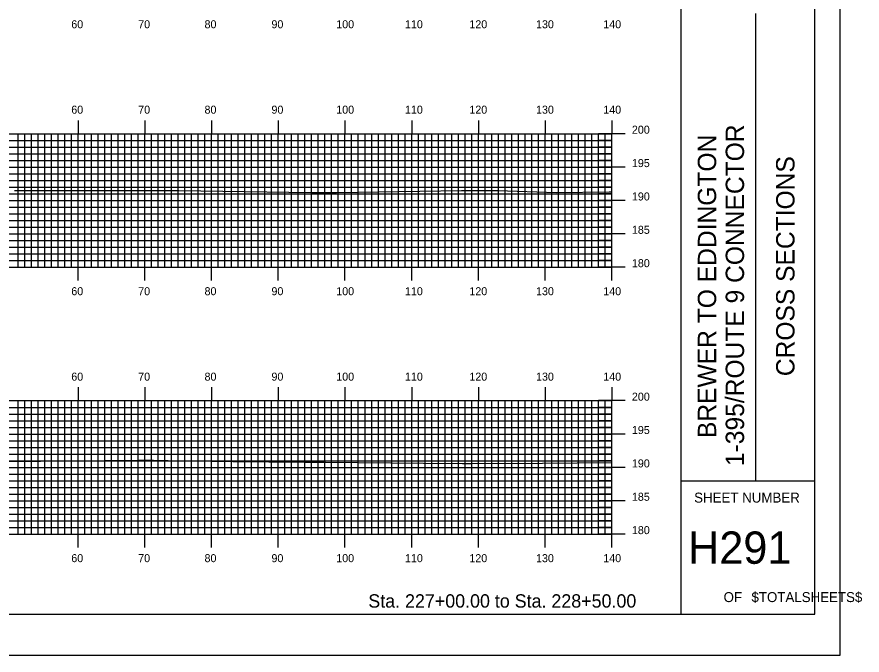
# Model space of a CAD drawing. Extents: x 1798781 to 1799124, y 442591 to 442811.
# Drawn here: x 1798997.8 to 1799124.5, y 442590.5 to 442686.2 of the extents above; entities that cross this region are included whole.
import ezdxf

# ---------------------------------------------------------------- set-up
doc = ezdxf.new("R2010")
doc.units = 0
for name, color, linetype in [('BORDER', 7, 'Continuous'), ('H_V ANNOTATION', 7, 'Continuous'), ('MAJOR', 7, 'Continuous'), ('MINOR', 7, 'Continuous'), ('PLOT BOUNDARY', 7, 'Continuous'), ('S_Roadway_Centerline', 7, 'Continuous')]:
    doc.layers.add(name, color=color, linetype=linetype)

msp = doc.modelspace()

# ---------------------------------------------------------------- linework, layer by layer
at = {"layer": 'BORDER'}
for p, q in [((1799097.38, 442596.67), (1799097.38, 442806.67)), ((1799108.57, 442616.67), (1799108.57, 442686.67)), ((1799097.38, 442616.67), (1799117.38, 442616.67))]:
    msp.add_line(p, q, dxfattribs=at)
msp.add_lwpolyline([(1798797.38, 442596.67), (1799117.38, 442596.67), (1799117.38, 442806.67), (1798797.38, 442806.67)], close=True, dxfattribs=at)
at = {"layer": 'MAJOR'}
for p, q in [((1799006.98, 442670.67), (1799006.98, 442668.67)), ((1799016.98, 442670.67), (1799016.98, 442668.67)), ((1799026.98, 442670.67), (1799026.98, 442668.67)), ((1799036.98, 442670.67), (1799036.98, 442668.67)), ((1799046.98, 442670.67), (1799046.98, 442668.67)), ((1799056.98, 442670.67), (1799056.98, 442668.67)), ((1799066.98, 442670.67), (1799066.98, 442668.67)), ((1799076.98, 442670.67), (1799076.98, 442668.67)), ((1799086.98, 442670.67), (1799086.98, 442668.67)), ((1798806.98, 442668.67), (1799086.98, 442668.67)), ((1798806.98, 442668.67), (1799086.98, 442668.67)), ((1799006.98, 442648.67), (1799006.98, 442668.67)), ((1799016.98, 442648.67), (1799016.98, 442668.67)), ((1799026.98, 442648.67), (1799026.98, 442668.67)), ((1799036.98, 442648.67), (1799036.98, 442668.67)), ((1799046.98, 442648.67), (1799046.98, 442668.67)), ((1799056.98, 442648.67), (1799056.98, 442668.67)), ((1799066.98, 442648.67), (1799066.98, 442668.67)), ((1799076.98, 442648.67), (1799076.98, 442668.67)), ((1799088.99, 442668.67), (1799084.98, 442668.67)), ((1799086.98, 442648.67), (1799086.98, 442668.67)), ((1799086.98, 442648.67), (1799086.98, 442668.67)), ((1798806.98, 442663.67), (1799086.98, 442663.67)), ((1799088.99, 442663.67), (1799084.98, 442663.67)), ((1798806.98, 442658.67), (1799086.98, 442658.67)), ((1799088.99, 442658.67), (1799084.98, 442658.67)), ((1798806.98, 442653.67), (1799086.98, 442653.67)), ((1799088.99, 442653.67), (1799084.98, 442653.67)), ((1798806.98, 442648.67), (1799086.98, 442648.67)), ((1798806.98, 442648.67), (1799086.98, 442648.67)), ((1799006.98, 442646.66), (1799006.98, 442648.67)), ((1799016.98, 442646.66), (1799016.98, 442648.67)), ((1799026.98, 442646.66), (1799026.98, 442648.67)), ((1799036.98, 442646.66), (1799036.98, 442648.67)), ((1799046.98, 442646.66), (1799046.98, 442648.67)), ((1799056.98, 442646.66), (1799056.98, 442648.67)), ((1799066.98, 442646.66), (1799066.98, 442648.67)), ((1799076.98, 442646.66), (1799076.98, 442648.67)), ((1799088.99, 442648.67), (1799084.98, 442648.67)), ((1799086.98, 442646.66), (1799086.98, 442648.67)), ((1799006.98, 442630.67), (1799006.98, 442628.67)), ((1799016.98, 442630.67), (1799016.98, 442628.67)), ((1799026.98, 442630.67), (1799026.98, 442628.67)), ((1799036.98, 442630.67), (1799036.98, 442628.67)), ((1799046.98, 442630.67), (1799046.98, 442628.67)), ((1799056.98, 442630.67), (1799056.98, 442628.67)), ((1799066.98, 442630.67), (1799066.98, 442628.67)), ((1799076.98, 442630.67), (1799076.98, 442628.67)), ((1799086.98, 442630.67), (1799086.98, 442628.67)), ((1798806.98, 442628.67), (1799086.98, 442628.67)), ((1798806.98, 442628.67), (1799086.98, 442628.67)), ((1799006.98, 442608.67), (1799006.98, 442628.67)), ((1799016.98, 442608.67), (1799016.98, 442628.67)), ((1799026.98, 442608.67), (1799026.98, 442628.67)), ((1799036.98, 442608.67), (1799036.98, 442628.67)), ((1799046.98, 442608.67), (1799046.98, 442628.67)), ((1799056.98, 442608.67), (1799056.98, 442628.67)), ((1799066.98, 442608.67), (1799066.98, 442628.67)), ((1799076.98, 442608.67), (1799076.98, 442628.67)), ((1799088.99, 442628.67), (1799084.98, 442628.67)), ((1799086.98, 442608.67), (1799086.98, 442628.67)), ((1799086.98, 442608.67), (1799086.98, 442628.67)), ((1798806.98, 442623.67), (1799086.98, 442623.67)), ((1799088.99, 442623.67), (1799084.98, 442623.67)), ((1798806.98, 442618.67), (1799086.98, 442618.67)), ((1799088.99, 442618.67), (1799084.98, 442618.67)), ((1798806.98, 442613.67), (1799086.98, 442613.67)), ((1799088.99, 442613.67), (1799084.98, 442613.67)), ((1798806.98, 442608.67), (1799086.98, 442608.67)), ((1798806.98, 442608.67), (1799086.98, 442608.67)), ((1799006.98, 442606.66), (1799006.98, 442608.67)), ((1799016.98, 442606.66), (1799016.98, 442608.67)), ((1799026.98, 442606.66), (1799026.98, 442608.67)), ((1799036.98, 442606.66), (1799036.98, 442608.67)), ((1799046.98, 442606.66), (1799046.98, 442608.67)), ((1799056.98, 442606.66), (1799056.98, 442608.67)), ((1799066.98, 442606.66), (1799066.98, 442608.67)), ((1799076.98, 442606.66), (1799076.98, 442608.67)), ((1799088.99, 442608.67), (1799084.98, 442608.67)), ((1799086.98, 442606.66), (1799086.98, 442608.67))]:
    msp.add_line(p, q, dxfattribs=at)
at = {"layer": 'MINOR'}
for p, q in [((1798997.98, 442648.67), (1798997.98, 442668.67)), ((1798998.98, 442648.67), (1798998.98, 442668.67)), ((1798999.98, 442648.67), (1798999.98, 442668.67)), ((1799000.98, 442648.67), (1799000.98, 442668.67)), ((1799001.98, 442648.67), (1799001.98, 442668.67)), ((1799002.98, 442648.67), (1799002.98, 442668.67)), ((1799003.98, 442648.67), (1799003.98, 442668.67)), ((1799004.98, 442648.67), (1799004.98, 442668.67)), ((1799005.98, 442648.67), (1799005.98, 442668.67)), ((1799007.98, 442648.67), (1799007.98, 442668.67)), ((1799008.98, 442648.67), (1799008.98, 442668.67)), ((1799009.98, 442648.67), (1799009.98, 442668.67)), ((1799010.98, 442648.67), (1799010.98, 442668.67)), ((1799011.98, 442648.67), (1799011.98, 442668.67)), ((1799012.98, 442648.67), (1799012.98, 442668.67)), ((1799013.98, 442648.67), (1799013.98, 442668.67)), ((1799014.98, 442648.67), (1799014.98, 442668.67)), ((1799015.98, 442648.67), (1799015.98, 442668.67)), ((1799017.98, 442648.67), (1799017.98, 442668.67)), ((1799018.98, 442648.67), (1799018.98, 442668.67)), ((1799019.98, 442648.67), (1799019.98, 442668.67)), ((1799020.98, 442648.67), (1799020.98, 442668.67)), ((1799021.98, 442648.67), (1799021.98, 442668.67)), ((1799022.98, 442648.67), (1799022.98, 442668.67)), ((1799023.98, 442648.67), (1799023.98, 442668.67)), ((1799024.98, 442648.67), (1799024.98, 442668.67)), ((1799025.98, 442648.67), (1799025.98, 442668.67)), ((1799027.98, 442648.67), (1799027.98, 442668.67)), ((1799028.98, 442648.67), (1799028.98, 442668.67)), ((1799029.98, 442648.67), (1799029.98, 442668.67)), ((1799030.98, 442648.67), (1799030.98, 442668.67)), ((1799031.98, 442648.67), (1799031.98, 442668.67)), ((1799032.98, 442648.67), (1799032.98, 442668.67)), ((1799033.98, 442648.67), (1799033.98, 442668.67)), ((1799034.98, 442648.67), (1799034.98, 442668.67)), ((1799035.98, 442648.67), (1799035.98, 442668.67)), ((1799037.98, 442648.67), (1799037.98, 442668.67)), ((1799038.98, 442648.67), (1799038.98, 442668.67)), ((1799039.98, 442648.67), (1799039.98, 442668.67)), ((1799040.98, 442648.67), (1799040.98, 442668.67)), ((1799041.98, 442648.67), (1799041.98, 442668.67)), ((1799042.98, 442648.67), (1799042.98, 442668.67)), ((1799043.98, 442648.67), (1799043.98, 442668.67)), ((1799044.98, 442648.67), (1799044.98, 442668.67)), ((1799045.98, 442648.67), (1799045.98, 442668.67)), ((1799047.98, 442648.67), (1799047.98, 442668.67)), ((1799048.98, 442648.67), (1799048.98, 442668.67)), ((1799049.98, 442648.67), (1799049.98, 442668.67)), ((1799050.98, 442648.67), (1799050.98, 442668.67)), ((1799051.98, 442648.67), (1799051.98, 442668.67)), ((1799052.98, 442648.67), (1799052.98, 442668.67)), ((1799053.98, 442648.67), (1799053.98, 442668.67)), ((1799054.98, 442648.67), (1799054.98, 442668.67)), ((1799055.98, 442648.67), (1799055.98, 442668.67)), ((1799057.98, 442648.67), (1799057.98, 442668.67)), ((1799058.98, 442648.67), (1799058.98, 442668.67)), ((1799059.98, 442648.67), (1799059.98, 442668.67)), ((1799060.98, 442648.67), (1799060.98, 442668.67)), ((1799061.98, 442648.67), (1799061.98, 442668.67)), ((1799062.98, 442648.67), (1799062.98, 442668.67)), ((1799063.98, 442648.67), (1799063.98, 442668.67)), ((1799064.98, 442648.67), (1799064.98, 442668.67)), ((1799065.98, 442648.67), (1799065.98, 442668.67)), ((1799067.98, 442648.67), (1799067.98, 442668.67)), ((1799068.98, 442648.67), (1799068.98, 442668.67)), ((1799069.98, 442648.67), (1799069.98, 442668.67)), ((1799070.98, 442648.67), (1799070.98, 442668.67)), ((1799071.98, 442648.67), (1799071.98, 442668.67)), ((1799072.98, 442648.67), (1799072.98, 442668.67)), ((1799073.98, 442648.67), (1799073.98, 442668.67)), ((1799074.98, 442648.67), (1799074.98, 442668.67)), ((1799075.98, 442648.67), (1799075.98, 442668.67)), ((1799077.98, 442648.67), (1799077.98, 442668.67)), ((1799078.98, 442648.67), (1799078.98, 442668.67)), ((1799079.98, 442648.67), (1799079.98, 442668.67)), ((1799080.98, 442648.67), (1799080.98, 442668.67)), ((1799081.98, 442648.67), (1799081.98, 442668.67)), ((1799082.98, 442648.67), (1799082.98, 442668.67)), ((1799083.98, 442648.67), (1799083.98, 442668.67)), ((1799084.98, 442648.67), (1799084.98, 442668.67)), ((1799085.98, 442648.67), (1799085.98, 442668.67)), ((1798806.98, 442667.67), (1799086.98, 442667.67)), ((1799086.98, 442667.67), (1799084.98, 442667.67)), ((1798806.98, 442666.67), (1799086.98, 442666.67)), ((1799086.98, 442666.67), (1799084.98, 442666.67)), ((1798806.98, 442665.67), (1799086.98, 442665.67)), ((1798806.98, 442664.67), (1799086.98, 442664.67)), ((1799086.98, 442665.67), (1799084.98, 442665.67)), ((1799086.98, 442664.67), (1799084.98, 442664.67)), ((1798806.98, 442662.67), (1799086.98, 442662.67)), ((1799086.98, 442662.67), (1799084.98, 442662.67)), ((1798806.98, 442661.67), (1799086.98, 442661.67)), ((1799086.98, 442661.67), (1799084.98, 442661.67)), ((1798806.98, 442660.67), (1799086.98, 442660.67)), ((1798806.98, 442659.67), (1799086.98, 442659.67)), ((1799086.98, 442660.67), (1799084.98, 442660.67)), ((1799086.98, 442659.67), (1799084.98, 442659.67)), ((1798806.98, 442657.67), (1799086.98, 442657.67)), ((1799086.98, 442657.67), (1799084.98, 442657.67)), ((1798806.98, 442656.67), (1799086.98, 442656.67)), ((1799086.98, 442656.67), (1799084.98, 442656.67)), ((1798806.98, 442655.67), (1799086.98, 442655.67)), ((1798806.98, 442654.67), (1799086.98, 442654.67)), ((1799086.98, 442655.67), (1799084.98, 442655.67)), ((1799086.98, 442654.67), (1799084.98, 442654.67)), ((1798806.98, 442652.67), (1799086.98, 442652.67)), ((1799086.98, 442652.67), (1799084.98, 442652.67)), ((1798806.98, 442651.67), (1799086.98, 442651.67)), ((1799086.98, 442651.67), (1799084.98, 442651.67)), ((1798806.98, 442650.67), (1799086.98, 442650.67)), ((1798806.98, 442649.67), (1799086.98, 442649.67)), ((1799086.98, 442650.67), (1799084.98, 442650.67)), ((1799086.98, 442649.67), (1799084.98, 442649.67)), ((1798997.98, 442608.67), (1798997.98, 442628.67)), ((1798998.98, 442608.67), (1798998.98, 442628.67)), ((1798999.98, 442608.67), (1798999.98, 442628.67)), ((1799000.98, 442608.67), (1799000.98, 442628.67)), ((1799001.98, 442608.67), (1799001.98, 442628.67)), ((1799002.98, 442608.67), (1799002.98, 442628.67)), ((1799003.98, 442608.67), (1799003.98, 442628.67)), ((1799004.98, 442608.67), (1799004.98, 442628.67)), ((1799005.98, 442608.67), (1799005.98, 442628.67)), ((1799007.98, 442608.67), (1799007.98, 442628.67)), ((1799008.98, 442608.67), (1799008.98, 442628.67)), ((1799009.98, 442608.67), (1799009.98, 442628.67)), ((1799010.98, 442608.67), (1799010.98, 442628.67)), ((1799011.98, 442608.67), (1799011.98, 442628.67)), ((1799012.98, 442608.67), (1799012.98, 442628.67)), ((1799013.98, 442608.67), (1799013.98, 442628.67)), ((1799014.98, 442608.67), (1799014.98, 442628.67)), ((1799015.98, 442608.67), (1799015.98, 442628.67)), ((1799017.98, 442608.67), (1799017.98, 442628.67)), ((1799018.98, 442608.67), (1799018.98, 442628.67)), ((1799019.98, 442608.67), (1799019.98, 442628.67)), ((1799020.98, 442608.67), (1799020.98, 442628.67)), ((1799021.98, 442608.67), (1799021.98, 442628.67)), ((1799022.98, 442608.67), (1799022.98, 442628.67)), ((1799023.98, 442608.67), (1799023.98, 442628.67)), ((1799024.98, 442608.67), (1799024.98, 442628.67)), ((1799025.98, 442608.67), (1799025.98, 442628.67)), ((1799027.98, 442608.67), (1799027.98, 442628.67)), ((1799028.98, 442608.67), (1799028.98, 442628.67)), ((1799029.98, 442608.67), (1799029.98, 442628.67)), ((1799030.98, 442608.67), (1799030.98, 442628.67)), ((1799031.98, 442608.67), (1799031.98, 442628.67)), ((1799032.98, 442608.67), (1799032.98, 442628.67)), ((1799033.98, 442608.67), (1799033.98, 442628.67)), ((1799034.98, 442608.67), (1799034.98, 442628.67)), ((1799035.98, 442608.67), (1799035.98, 442628.67)), ((1799037.98, 442608.67), (1799037.98, 442628.67)), ((1799038.98, 442608.67), (1799038.98, 442628.67)), ((1799039.98, 442608.67), (1799039.98, 442628.67)), ((1799040.98, 442608.67), (1799040.98, 442628.67)), ((1799041.98, 442608.67), (1799041.98, 442628.67)), ((1799042.98, 442608.67), (1799042.98, 442628.67)), ((1799043.98, 442608.67), (1799043.98, 442628.67)), ((1799044.98, 442608.67), (1799044.98, 442628.67)), ((1799045.98, 442608.67), (1799045.98, 442628.67)), ((1799047.98, 442608.67), (1799047.98, 442628.67)), ((1799048.98, 442608.67), (1799048.98, 442628.67)), ((1799049.98, 442608.67), (1799049.98, 442628.67)), ((1799050.98, 442608.67), (1799050.98, 442628.67)), ((1799051.98, 442608.67), (1799051.98, 442628.67)), ((1799052.98, 442608.67), (1799052.98, 442628.67)), ((1799053.98, 442608.67), (1799053.98, 442628.67)), ((1799054.98, 442608.67), (1799054.98, 442628.67)), ((1799055.98, 442608.67), (1799055.98, 442628.67)), ((1799057.98, 442608.67), (1799057.98, 442628.67)), ((1799058.98, 442608.67), (1799058.98, 442628.67)), ((1799059.98, 442608.67), (1799059.98, 442628.67)), ((1799060.98, 442608.67), (1799060.98, 442628.67)), ((1799061.98, 442608.67), (1799061.98, 442628.67)), ((1799062.98, 442608.67), (1799062.98, 442628.67)), ((1799063.98, 442608.67), (1799063.98, 442628.67)), ((1799064.98, 442608.67), (1799064.98, 442628.67)), ((1799065.98, 442608.67), (1799065.98, 442628.67)), ((1799067.98, 442608.67), (1799067.98, 442628.67)), ((1799068.98, 442608.67), (1799068.98, 442628.67)), ((1799069.98, 442608.67), (1799069.98, 442628.67)), ((1799070.98, 442608.67), (1799070.98, 442628.67)), ((1799071.98, 442608.67), (1799071.98, 442628.67)), ((1799072.98, 442608.67), (1799072.98, 442628.67)), ((1799073.98, 442608.67), (1799073.98, 442628.67)), ((1799074.98, 442608.67), (1799074.98, 442628.67)), ((1799075.98, 442608.67), (1799075.98, 442628.67)), ((1799077.98, 442608.67), (1799077.98, 442628.67)), ((1799078.98, 442608.67), (1799078.98, 442628.67)), ((1799079.98, 442608.67), (1799079.98, 442628.67)), ((1799080.98, 442608.67), (1799080.98, 442628.67)), ((1799081.98, 442608.67), (1799081.98, 442628.67)), ((1799082.98, 442608.67), (1799082.98, 442628.67)), ((1799083.98, 442608.67), (1799083.98, 442628.67)), ((1799084.98, 442608.67), (1799084.98, 442628.67)), ((1799085.98, 442608.67), (1799085.98, 442628.67)), ((1798806.98, 442627.67), (1799086.98, 442627.67)), ((1798806.98, 442626.67), (1799086.98, 442626.67)), ((1799086.98, 442627.67), (1799084.98, 442627.67)), ((1799086.98, 442626.67), (1799084.98, 442626.67)), ((1798806.98, 442625.67), (1799086.98, 442625.67)), ((1799086.98, 442625.67), (1799084.98, 442625.67)), ((1798806.98, 442624.67), (1799086.98, 442624.67)), ((1799086.98, 442624.67), (1799084.98, 442624.67)), ((1798806.98, 442622.67), (1799086.98, 442622.67)), ((1798806.98, 442621.67), (1799086.98, 442621.67)), ((1799086.98, 442622.67), (1799084.98, 442622.67)), ((1799086.98, 442621.67), (1799084.98, 442621.67)), ((1798806.98, 442620.67), (1799086.98, 442620.67)), ((1799086.98, 442620.67), (1799084.98, 442620.67)), ((1798806.98, 442619.67), (1799086.98, 442619.67)), ((1799086.98, 442619.67), (1799084.98, 442619.67)), ((1798806.98, 442617.67), (1799086.98, 442617.67)), ((1798806.98, 442616.67), (1799086.98, 442616.67)), ((1799086.98, 442617.67), (1799084.98, 442617.67)), ((1799086.98, 442616.67), (1799084.98, 442616.67)), ((1798806.98, 442615.67), (1799086.98, 442615.67)), ((1799086.98, 442615.67), (1799084.98, 442615.67)), ((1798806.98, 442614.67), (1799086.98, 442614.67)), ((1799086.98, 442614.67), (1799084.98, 442614.67)), ((1798806.98, 442612.67), (1799086.98, 442612.67)), ((1798806.98, 442611.67), (1799086.98, 442611.67)), ((1799086.98, 442612.67), (1799084.98, 442612.67)), ((1799086.98, 442611.67), (1799084.98, 442611.67)), ((1798806.98, 442610.67), (1799086.98, 442610.67)), ((1799086.98, 442610.67), (1799084.98, 442610.67)), ((1798806.98, 442609.67), (1799086.98, 442609.67)), ((1799086.98, 442609.67), (1799084.98, 442609.67))]:
    msp.add_line(p, q, dxfattribs=at)
at = {"layer": 'PLOT BOUNDARY'}
msp.add_lwpolyline([(1798781.2, 442590.55), (1799121.2, 442590.55), (1799121.2, 442810.55), (1798781.2, 442810.55)], close=True, dxfattribs=at)
at = {"layer": 'S_Roadway_Centerline'}
for points in [[(1798997.44, 442660.14), (1798998.09, 442660.14), (1799018.62, 442660.17), (1799022.08, 442660.15), (1799041.85, 442659.84), (1799045.7, 442659.85), (1799064.42, 442660.14), (1799067.06, 442660.18), (1799069.88, 442660.14), (1799078.65, 442659.88), (1799086.58, 442659.96), (1799086.98, 442659.97)], [(1798996.49, 442619.54), (1799015.91, 442619.74), (1799018.29, 442619.73), (1799020.48, 442619.72), (1799030.15, 442619.57), (1799040.91, 442619.45), (1799044.04, 442619.43), (1799058.73, 442619.31), (1799064.58, 442619.26), (1799065.83, 442619.26), (1799076.58, 442619.32), (1799086.98, 442619.4)]]:
    msp.add_lwpolyline(points, dxfattribs=at)

# ---------------------------------------------------------------- texts
at = {"layer": 'BORDER'}
for s, p in [('1-395/ROUTE 9 CONNECTOR', (1799106.79, 442618.87)), ('BREWER TO EDDINGTON', (1799102.61, 442623.07)), ('CROSS SECTIONS', (1799114.35, 442632.34))]:
    msp.add_text(s, height=2.7557, rotation=90, dxfattribs=at).set_placement(p)
for s, height, p in [('SHEET NUMBER', 1.4905, (1799099.31, 442613.4)), ('H291', 4.839, (1799098.41, 442604.23)), ('$TOTALSHEETS$', 1.4905, (1799107.9, 442598.49)), ('OF', 1.491, (1799103.72, 442598.49))]:
    msp.add_text(s, height=height, dxfattribs=at).set_placement(p)
at = {"layer": 'H_V ANNOTATION'}
for s, height, p in [('60', 1.2, (1799005.96, 442684.47)), ('70', 1.2, (1799015.99, 442684.47)), ('80', 1.2, (1799025.93, 442684.47)), ('90', 1.2, (1799035.96, 442684.47)), ('100', 1.2, (1799045.67, 442684.47)), ('110', 1.2, (1799055.97, 442684.47)), ('120', 1.2, (1799065.62, 442684.47)), ('130', 1.2, (1799075.61, 442684.47)), ('140', 1.2, (1799085.69, 442684.47)), ('60', 1.2, (1799005.96, 442671.67)), ('70', 1.2, (1799015.99, 442671.67)), ('80', 1.2, (1799025.93, 442671.67)), ('90', 1.2, (1799035.96, 442671.67)), ('100', 1.2, (1799045.67, 442671.67)), ('110', 1.2, (1799055.97, 442671.67)), ('120', 1.2, (1799065.62, 442671.67)), ('130', 1.2, (1799075.61, 442671.67)), ('140', 1.2, (1799085.69, 442671.67)), ('200', 1.2, (1799089.98, 442668.67)), ('195', 1.2, (1799089.98, 442663.67)), ('190', 1.2, (1799089.98, 442658.67)), ('185', 1.2, (1799089.98, 442653.67)), ('180', 1.2, (1799089.98, 442648.67)), ('60', 1.2, (1799005.96, 442644.47)), ('70', 1.2, (1799015.99, 442644.47)), ('80', 1.2, (1799025.93, 442644.47)), ('90', 1.2, (1799035.96, 442644.47)), ('100', 1.2, (1799045.67, 442644.47)), ('110', 1.2, (1799055.97, 442644.47)), ('120', 1.2, (1799065.62, 442644.47)), ('130', 1.2, (1799075.61, 442644.47)), ('140', 1.2, (1799085.69, 442644.47)), ('60', 1.2, (1799005.96, 442631.67)), ('70', 1.2, (1799015.99, 442631.67)), ('80', 1.2, (1799025.93, 442631.67)), ('90', 1.2, (1799035.96, 442631.67)), ('100', 1.2, (1799045.67, 442631.67)), ('110', 1.2, (1799055.97, 442631.67)), ('120', 1.2, (1799065.62, 442631.67)), ('130', 1.2, (1799075.61, 442631.67)), ('140', 1.2, (1799085.69, 442631.67)), ('200', 1.2, (1799089.98, 442628.67)), ('195', 1.2, (1799089.98, 442623.67)), ('190', 1.2, (1799089.98, 442618.67)), ('185', 1.2, (1799089.98, 442613.67)), ('180', 1.2, (1799089.98, 442608.67)), ('60', 1.2, (1799005.96, 442604.47)), ('70', 1.2, (1799015.99, 442604.47)), ('80', 1.2, (1799025.93, 442604.47)), ('90', 1.2, (1799035.96, 442604.47)), ('100', 1.2, (1799045.67, 442604.47)), ('110', 1.2, (1799055.97, 442604.47)), ('120', 1.2, (1799065.62, 442604.47)), ('130', 1.2, (1799075.61, 442604.47)), ('140', 1.2, (1799085.69, 442604.47)), ('Sta. 227+00.00 to Sta. 228+50.00', 2.0004, (1799050.48, 442597.66))]:
    msp.add_text(s, height=height, dxfattribs=at).set_placement(p)

doc.saveas('drawing.dxf')
